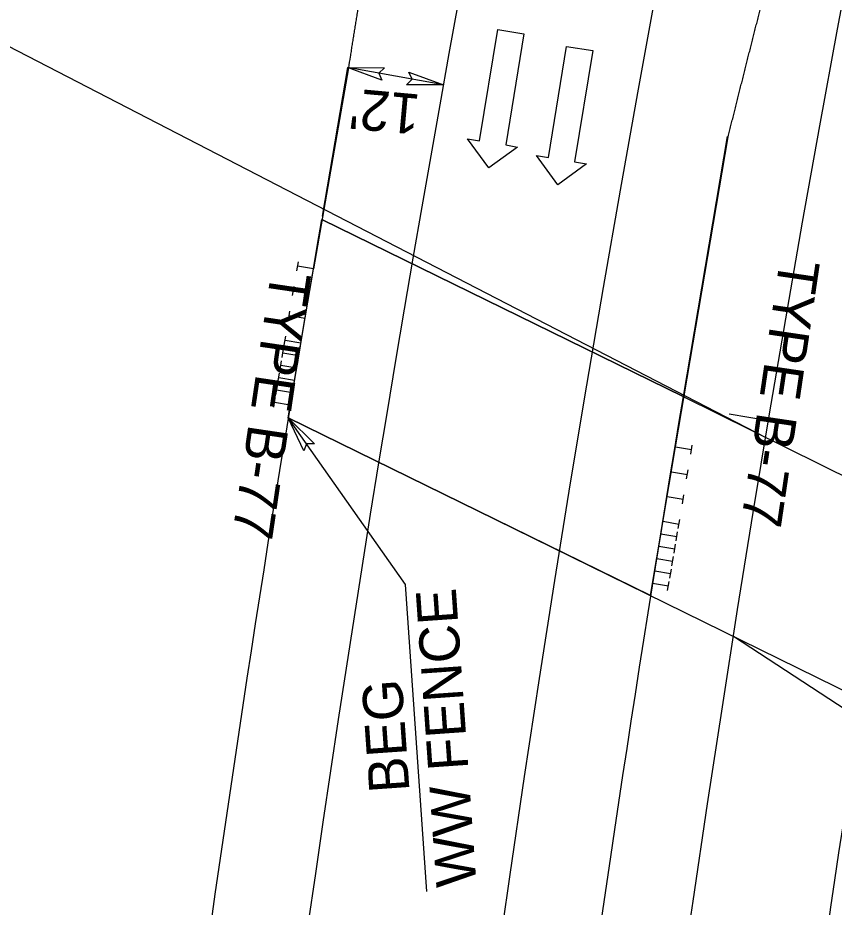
# Model space of a CAD drawing. Extents: x 2389099 to 2405615, y 552200 to 573532.
# Drawn here: x 2400098.2 to 2400199.7, y 568453.2 to 568563.8 of the extents above; entities that cross this region are included whole.
import ezdxf

# ---------------------------------------------------------------- set-up
doc = ezdxf.new("R2010")
doc.units = 0
for name, color, linetype in [('Prop Approach Slab', 7, 'Continuous'), ('Prop Approach Slab Hatching', 7, 'Continuous'), ('Prop Dimension', 7, 'Continuous'), ('Prop Dimension Text', 7, 'Continuous'), ('Prop DSN Text', 7, 'Continuous'), ('Prop EOT', 7, 'Continuous'), ('Prop Guardrail', 7, 'Continuous'), ('Prop Horizontal Alignment', 7, 'Continuous'), ('Prop Horizontal Alignment Tick Small', 7, 'Continuous'), ('Prop Lane Arrow Through CELL', 7, 'Continuous'), ('Prop SAU III Approach CELL', 7, 'Continuous')]:
    doc.layers.add(name, color=color, linetype=linetype)

msp = doc.modelspace()

# ---------------------------------------------------------------- linework, layer by layer
at = {"layer": 'Prop Approach Slab'}
for p, q in [((2400180.92, 568516.69), (2400135.99, 568538.72)), ((2400131.83, 568514.07), (2400176.88, 568491.95))]:
    msp.add_line(p, q, dxfattribs=at)
for radius, start, end in [(2959, 170.18806, 174.3984), (2911, 170.46446, 174.75565), (2883, 170.63278, 174.96393)]:
    msp.add_arc((2403051.7, 568034.46), radius, start, end, dxfattribs=at)
at = {"layer": 'Prop Approach Slab Hatching'}
msp.add_lwpolyline([(2400135.99, 568538.72), (2400180.92, 568516.69), (2400176.88, 568491.95), (2400131.83, 568514.07)], close=True, dxfattribs=at)
at = {"layer": 'Prop Dimension'}
for p, q in [((2400062.64, 568578), (2400191.22, 568511.59)), ((2400151.12, 568555.45), (2400139.19, 568557.59)), ((2400180.92, 568516.69), (2400207.15, 568503.7)), ((2400242.69, 568459.61), (2400131.83, 568514.07)), ((2400266.6, 568434.86), (2400187.21, 568486.87))]:
    msp.add_line(p, q, dxfattribs=at)
for points in [[(2400143.48, 568556.04), (2400139.19, 568557.59), (2400143.79, 568557.58), (2400143.08, 568556.9)], [(2400146.83, 568557.01), (2400151.12, 568555.45), (2400146.53, 568555.46), (2400147.23, 568556.15)], [(2400133.78, 568509.95), (2400131.83, 568514.07), (2400135.09, 568510.83), (2400134.1, 568510.84)]]:
    msp.add_lwpolyline(points, close=True, dxfattribs=at)
at = {"layer": 'Prop DSN Text'}
for p, q in [((2400146.4, 568493.32), (2400131.83, 568514.07)), ((2400149.07, 568455.19), (2400146.4, 568493.32))]:
    msp.add_line(p, q, dxfattribs=at)
at = {"layer": 'Prop EOT'}
for p, q in [((2400139.19, 568557.59), (2400136.06, 568539.11)), ((2400186.41, 568549.02), (2400180.94, 568516.69))]:
    msp.add_line(p, q, dxfattribs=at)
for radius, start in [(2923, 119.41161), (2877, 119.41161), (2947, 148.75529), (2853, 154.68245)]:
    msp.add_arc((2403051.7, 568034.46), radius, start, 180.94658, dxfattribs=at)
for points in [[(2400147.78, 568607.9), (2400147.66, 568607.21), (2400147.54, 568606.54), (2400147.42, 568605.86), (2400147.3, 568605.18), (2400147.18, 568604.5), (2400147.06, 568603.82), (2400146.94, 568603.14), (2400146.82, 568602.47), (2400146.7, 568601.78), (2400146.58, 568601.1), (2400146.47, 568600.43), (2400146.35, 568599.74), (2400146.23, 568599.07), (2400146.11, 568598.38), (2400145.99, 568597.71), (2400145.87, 568597.03), (2400145.76, 568596.34), (2400145.64, 568595.67), (2400145.52, 568594.98), (2400145.41, 568594.31), (2400145.29, 568593.63), (2400145.17, 568592.95), (2400145.05, 568592.27), (2400144.94, 568591.58), (2400144.82, 568590.91), (2400144.7, 568590.23), (2400144.59, 568589.55), (2400144.47, 568588.87), (2400144.36, 568588.19), (2400144.24, 568587.51), (2400144.12, 568586.82), (2400144.01, 568586.15), (2400143.89, 568585.47), (2400143.78, 568584.79), (2400143.66, 568584.11), (2400143.55, 568583.43), (2400143.44, 568582.75), (2400143.32, 568582.06), (2400143.21, 568581.39), (2400143.09, 568580.7), (2400142.98, 568580.03), (2400142.87, 568579.35), (2400142.75, 568578.67), (2400142.64, 568577.99), (2400142.52, 568577.3), (2400142.41, 568576.63), (2400142.3, 568575.94), (2400142.19, 568575.27), (2400142.07, 568574.58), (2400141.96, 568573.91), (2400141.85, 568573.22), (2400141.74, 568572.55), (2400141.62, 568571.86), (2400141.51, 568571.18), (2400141.4, 568570.51), (2400141.29, 568569.82), (2400141.18, 568569.15), (2400141.07, 568568.46), (2400140.96, 568567.79), (2400140.85, 568567.1), (2400140.73, 568566.42), (2400140.62, 568565.74), (2400140.51, 568565.06), (2400140.4, 568564.38), (2400140.29, 568563.7), (2400140.18, 568563.02), (2400140.07, 568562.33), (2400139.96, 568561.65), (2400139.85, 568560.97), (2400139.74, 568560.29), (2400139.64, 568559.61), (2400139.53, 568558.93), (2400139.31, 568557.57)], [(2400186.54, 568549), (2400186.71, 568549.69), (2400186.88, 568550.38), (2400187.05, 568551.06), (2400187.23, 568551.76), (2400187.4, 568552.44), (2400187.57, 568553.12), (2400187.74, 568553.82), (2400187.91, 568554.5), (2400188.08, 568555.18), (2400188.26, 568555.87), (2400188.43, 568556.56), (2400188.6, 568557.25), (2400188.78, 568557.93), (2400188.95, 568558.61), (2400189.12, 568559.31), (2400189.3, 568559.99), (2400189.47, 568560.68), (2400189.65, 568561.36), (2400189.82, 568562.05), (2400189.99, 568562.74), (2400190.17, 568563.42), (2400190.34, 568564.1), (2400190.52, 568564.79), (2400190.69, 568565.48), (2400190.87, 568566.17), (2400191.04, 568566.85), (2400191.22, 568567.53), (2400191.39, 568568.22), (2400191.57, 568568.91), (2400191.74, 568569.59), (2400191.92, 568570.28), (2400192.1, 568570.96), (2400192.27, 568571.65), (2400192.45, 568572.33), (2400192.63, 568573.02), (2400192.8, 568573.71), (2400192.98, 568574.39), (2400193.16, 568575.08), (2400193.34, 568575.76), (2400193.51, 568576.44), (2400193.69, 568577.13), (2400193.87, 568577.81), (2400194.05, 568578.49), (2400194.23, 568579.19), (2400194.4, 568579.87), (2400194.58, 568580.56), (2400194.76, 568581.24), (2400194.94, 568581.92), (2400195.12, 568582.61), (2400195.3, 568583.29), (2400195.48, 568583.98), (2400195.66, 568584.66), (2400195.84, 568585.34), (2400196.02, 568586.03), (2400196.2, 568586.71), (2400196.38, 568587.39), (2400196.56, 568588.08), (2400196.74, 568588.76), (2400196.92, 568589.45), (2400197.1, 568590.13), (2400197.28, 568590.81), (2400197.46, 568591.5), (2400197.64, 568592.18), (2400197.82, 568592.87), (2400198.01, 568593.55), (2400198.19, 568594.23), (2400198.37, 568594.92), (2400198.55, 568595.6), (2400198.73, 568596.28), (2400198.92, 568596.97), (2400199.1, 568597.65), (2400199.28, 568598.34), (2400199.46, 568599.02), (2400199.65, 568599.7)]]:
    msp.add_spline(points, degree=3, dxfattribs=at)
at = {"layer": 'Prop Guardrail'}
for p, q in [((2400139.31, 568557.57), (2400134.96, 568532.56)), ((2400180, 568510.43), (2400186.54, 568549))]:
    msp.add_line(p, q, dxfattribs=at)
for points in [[(2400147.78, 568607.9), (2400147.66, 568607.21), (2400147.54, 568606.54), (2400147.42, 568605.86), (2400147.3, 568605.18), (2400147.18, 568604.5), (2400147.06, 568603.82), (2400146.94, 568603.14), (2400146.82, 568602.47), (2400146.7, 568601.78), (2400146.58, 568601.1), (2400146.47, 568600.43), (2400146.35, 568599.74), (2400146.23, 568599.07), (2400146.11, 568598.38), (2400145.99, 568597.71), (2400145.87, 568597.03), (2400145.76, 568596.34), (2400145.64, 568595.67), (2400145.52, 568594.98), (2400145.41, 568594.31), (2400145.29, 568593.63), (2400145.17, 568592.95), (2400145.05, 568592.27), (2400144.94, 568591.58), (2400144.82, 568590.91), (2400144.7, 568590.23), (2400144.59, 568589.55), (2400144.47, 568588.87), (2400144.36, 568588.19), (2400144.24, 568587.51), (2400144.12, 568586.82), (2400144.01, 568586.15), (2400143.89, 568585.47), (2400143.78, 568584.79), (2400143.66, 568584.11), (2400143.55, 568583.43), (2400143.44, 568582.75), (2400143.32, 568582.06), (2400143.21, 568581.39), (2400143.09, 568580.7), (2400142.98, 568580.03), (2400142.87, 568579.35), (2400142.75, 568578.67), (2400142.64, 568577.99), (2400142.52, 568577.3), (2400142.41, 568576.63), (2400142.3, 568575.94), (2400142.19, 568575.27), (2400142.07, 568574.58), (2400141.96, 568573.91), (2400141.85, 568573.22), (2400141.74, 568572.55), (2400141.62, 568571.86), (2400141.51, 568571.18), (2400141.4, 568570.51), (2400141.29, 568569.82), (2400141.18, 568569.15), (2400141.07, 568568.46), (2400140.96, 568567.79), (2400140.85, 568567.1), (2400140.73, 568566.42), (2400140.62, 568565.74), (2400140.51, 568565.06), (2400140.4, 568564.38), (2400140.29, 568563.7), (2400140.18, 568563.02), (2400140.07, 568562.33), (2400139.96, 568561.65), (2400139.85, 568560.97), (2400139.74, 568560.29), (2400139.64, 568559.61), (2400139.53, 568558.93), (2400139.31, 568557.57)], [(2400186.54, 568549), (2400186.71, 568549.69), (2400186.88, 568550.38), (2400187.05, 568551.06), (2400187.23, 568551.76), (2400187.4, 568552.44), (2400187.57, 568553.12), (2400187.74, 568553.82), (2400187.91, 568554.5), (2400188.08, 568555.18), (2400188.26, 568555.87), (2400188.43, 568556.56), (2400188.6, 568557.25), (2400188.78, 568557.93), (2400188.95, 568558.61), (2400189.12, 568559.31), (2400189.3, 568559.99), (2400189.47, 568560.68), (2400189.65, 568561.36), (2400189.82, 568562.05), (2400189.99, 568562.74), (2400190.17, 568563.42), (2400190.34, 568564.1), (2400190.52, 568564.79), (2400190.69, 568565.48), (2400190.87, 568566.17), (2400191.04, 568566.85), (2400191.22, 568567.53), (2400191.39, 568568.22), (2400191.57, 568568.91), (2400191.74, 568569.59), (2400191.92, 568570.28), (2400192.1, 568570.96), (2400192.27, 568571.65), (2400192.45, 568572.33), (2400192.63, 568573.02), (2400192.8, 568573.71), (2400192.98, 568574.39), (2400193.16, 568575.08), (2400193.34, 568575.76), (2400193.51, 568576.44), (2400193.69, 568577.13), (2400193.87, 568577.81), (2400194.05, 568578.49), (2400194.23, 568579.19), (2400194.4, 568579.87), (2400194.58, 568580.56), (2400194.76, 568581.24), (2400194.94, 568581.92), (2400195.12, 568582.61), (2400195.3, 568583.29), (2400195.48, 568583.98), (2400195.66, 568584.66), (2400195.84, 568585.34), (2400196.02, 568586.03), (2400196.2, 568586.71), (2400196.38, 568587.39), (2400196.56, 568588.08), (2400196.74, 568588.76), (2400196.92, 568589.45), (2400197.1, 568590.13), (2400197.28, 568590.81), (2400197.46, 568591.5), (2400197.64, 568592.18), (2400197.82, 568592.87), (2400198.01, 568593.55), (2400198.19, 568594.23), (2400198.37, 568594.92), (2400198.55, 568595.6), (2400198.73, 568596.28), (2400198.92, 568596.97), (2400199.1, 568597.65), (2400199.28, 568598.34), (2400199.46, 568599.02), (2400199.65, 568599.7)]]:
    msp.add_spline(points, degree=3, dxfattribs=at)
at = {"layer": 'Prop Horizontal Alignment'}
msp.add_arc((2403051.7, 568034.46), 2900, 119.41161, 180.94658, dxfattribs=at)
at = {"layer": 'Prop Horizontal Alignment Tick Small'}
msp.add_line((2400191.57, 568513.69), (2400186.64, 568514.52), dxfattribs=at)
at = {"layer": 'Prop Lane Arrow Through CELL'}
for p, q in [((2400155.61, 568548.5), (2400157.88, 568562.32)), ((2400157.88, 568562.32), (2400161.13, 568561.78)), ((2400161.13, 568561.78), (2400158.87, 568547.97)), ((2400164.18, 568546.42), (2400166.45, 568560.23)), ((2400166.45, 568560.23), (2400169.71, 568559.7)), ((2400169.71, 568559.7), (2400167.44, 568545.88)), ((2400156.78, 568545.12), (2400154.13, 568548.74)), ((2400154.13, 568548.74), (2400155.61, 568548.5)), ((2400160.34, 568547.72), (2400156.78, 568545.12)), ((2400158.87, 568547.97), (2400160.34, 568547.72)), ((2400165.35, 568543.03), (2400162.7, 568546.66)), ((2400162.7, 568546.66), (2400164.18, 568546.42)), ((2400168.92, 568545.64), (2400165.35, 568543.03)), ((2400167.44, 568545.88), (2400168.92, 568545.64))]:
    msp.add_line(p, q, dxfattribs=at)
at = {"layer": 'Prop SAU III Approach CELL'}
for p, q in [((2400132.9, 568532.33), (2400133.09, 568533.46)), ((2400131.83, 568514.07), (2400134.96, 568532.56)), ((2400134.96, 568532.56), (2400132.99, 568532.89)), ((2400132.37, 568529.25), (2400132.56, 568530.38)), ((2400134.44, 568529.48), (2400132.47, 568529.81)), ((2400131.85, 568526.17), (2400132.04, 568527.3)), ((2400133.92, 568526.4), (2400131.95, 568526.73)), ((2400131.33, 568523.09), (2400131.52, 568524.22)), ((2400133.4, 568523.32), (2400131.43, 568523.65)), ((2400131.07, 568521.55), (2400131.26, 568522.68)), ((2400130.81, 568520.01), (2400131, 568521.13)), ((2400133.14, 568521.78), (2400131.16, 568522.11)), ((2400132.88, 568520.24), (2400130.9, 568520.57)), ((2400130.55, 568518.46), (2400130.74, 568519.59)), ((2400132.61, 568518.7), (2400130.64, 568519.03)), ((2400130.29, 568516.92), (2400130.48, 568518.05)), ((2400132.35, 568517.15), (2400130.38, 568517.49)), ((2400130.02, 568515.38), (2400130.22, 568516.51)), ((2400132.09, 568515.61), (2400130.12, 568515.95)), ((2400176.88, 568491.95), (2400180, 568510.43)), ((2400180, 568510.43), (2400181.98, 568510.1)), ((2400181.88, 568509.53), (2400182.07, 568510.66)), ((2400179.48, 568507.35), (2400181.46, 568507.02)), ((2400181.36, 568506.45), (2400181.55, 568507.58)), ((2400180.84, 568503.37), (2400181.03, 568504.5)), ((2400178.96, 568504.27), (2400180.93, 568503.94)), ((2400178.44, 568501.19), (2400180.41, 568500.85)), ((2400180.32, 568500.29), (2400180.51, 568501.42)), ((2400178.18, 568499.65), (2400180.15, 568499.31)), ((2400180.06, 568498.75), (2400180.25, 568499.88)), ((2400177.92, 568498.11), (2400179.89, 568497.77)), ((2400179.8, 568497.21), (2400179.99, 568498.34)), ((2400179.54, 568495.67), (2400179.73, 568496.8)), ((2400177.66, 568496.57), (2400179.63, 568496.23)), ((2400177.4, 568495.03), (2400179.37, 568494.69)), ((2400179.27, 568494.13), (2400179.47, 568495.26)), ((2400177.14, 568493.49), (2400179.11, 568493.15)), ((2400179.01, 568492.59), (2400179.2, 568493.72))]:
    msp.add_line(p, q, dxfattribs=at)

# ---------------------------------------------------------------- texts
at = {"layer": 'Prop Dimension Text'}
for s, rotation, p in [("12'", 174.8377, (2400148.39, 568554.22)), ('TYPE B-77', 261.5853, (2400193, 568534.01)), ('TYPE B-77', 261.5853, (2400129.74, 568532.5))]:
    msp.add_text(s, height=5, rotation=rotation, dxfattribs=at).set_placement(p)
at = {"layer": 'Prop DSN Text'}
for s, p in [('WW FENCE', (2400155.25, 568455.93)), ('BEG', (2400146.92, 568467.62))]:
    msp.add_text(s, height=5, rotation=93.9999, dxfattribs=at).set_placement(p)

doc.saveas('drawing.dxf')
